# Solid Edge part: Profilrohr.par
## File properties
Username: bmolnar
Dokumentum tartalom típus: 0
Author: bmolnar
Last saved by: bmolnar
Revision: 91
Sűrűség: 0,000 kg/m^3
Pontosság: 0,990
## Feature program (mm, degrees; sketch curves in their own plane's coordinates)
base feature "unnamed BaseFeature 1"
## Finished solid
Body 1: solid body, 95 faces, 278 edges, 184 vertices.
  Faces by surface: plane 48, cylinder 47
  Edges by curve: line 184, circle 94
Bounding box of the edges (mm): 65.500 x 65.500 x 141.000, from (-32.75, -32.75, 0) to (32.75, 32.75, 141).
Cylindrical faces by radius (mm): R0.15 x20, R0.25 x20, R6.5 x2, R8 x4, R25 x1
Planar faces by outward normal: +x 11, +y 12, +z 1, -x 11, -y 12, -z 1
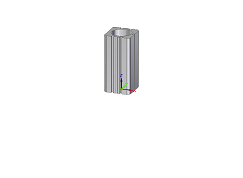
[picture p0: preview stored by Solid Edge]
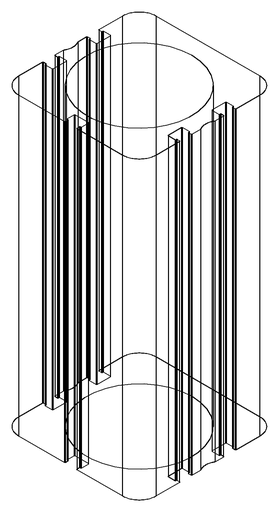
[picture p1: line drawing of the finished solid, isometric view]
